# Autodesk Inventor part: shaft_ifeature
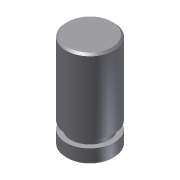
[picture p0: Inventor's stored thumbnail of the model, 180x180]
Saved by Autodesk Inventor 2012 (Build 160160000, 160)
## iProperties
Created: 2011-07
Part Number: shaft_ifeature
Material: Default
Document SubType Name: Modeling
Designer: CadCim
Density: 1 g/cm^3
Author: CadCim
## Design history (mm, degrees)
sketch "Sketch1"
  geometry: 1 further point
sketch "Sketch2"
  geometry: C1 r 25 at (0, 0); 1 further point
  constraints: 1 centre point, 1 coincident
  dimensions: "d0" = 50 diameter of C1
extrude "Extrusion1" new body sketch "Sketch2" distance "d1" = 100; taper "d2" = 0 deg
chamfer "Chamfer1" distance "d3" = 2; stored, may be unused: second distance "d4" = 2, angle "d5" = 45 deg
sketch "Sketch3"
  geometry: L1 (25, 23)-(20, 23); L2 (20, 23)-(20, 15); L3 (20, 15)-(25, 15); L4 (25, 15)-(25, 23); L5 (0, -20)-(0, 120) reference; 1 further point
  constraints: 8 end point, 2 parallel, 1 horizontal, 1 perpendicular
  dimensions: "d6" = 20 horizontal distance of L2.end point (0, 0); "d7" = 25 distance from line of point (0, 0) L4; "d8" = 15 distance from line of L3 point (0, 0); "d9" = 8 distance of L3.end L1.start
revolve "Revolution1" sketch "Sketch3" stored, may be unused: angle "d10" = 90 deg
body "Solid1"
